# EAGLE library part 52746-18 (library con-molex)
FPC Connector ZIF for SMT 0.5mm Source: http://www.farnell.com/datasheets/73044.pdf [DWG. NO. (Sheet 1 OF 2) SD-52746-**17]
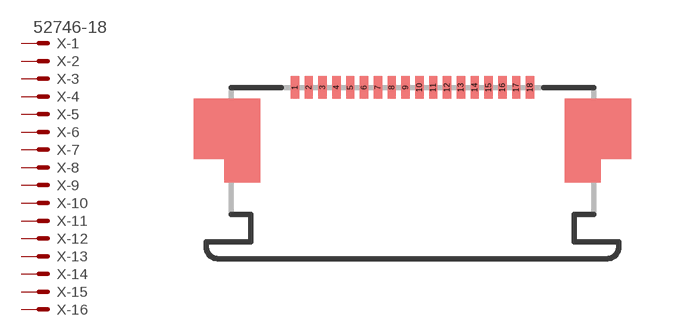
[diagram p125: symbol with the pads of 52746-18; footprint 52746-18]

Designator prefix X; gates -1=MV -2=M -3=M -4=M -5=M -6=M -7=M -8=M -9=M -10=M -11=M -12=M -13=M -14=M -15=M -16=M -17=M -18=M

## 52746-18 (MPN: 52746-1870; OC_FARNELL: unknown; OC_NEWARK: 92M6420)  [52746-18]
1  -1:S  pas
2  -2:S  pas
3  -3:S  pas
4  -4:S  pas
5  -5:S  pas
6  -6:S  pas
7  -7:S  pas
8  -8:S  pas
9  -9:S  pas
10  -10:S  pas
11  -11:S  pas
12  -12:S  pas
13  -13:S  pas
14  -14:S  pas
15  -15:S  pas
16  -16:S  pas
17  -17:S  pas
18  -18:S  pas

## Footprint 52746-18 (pad centres in mm)
FPC Connector ZIF for SMT 0.5mm Source: http://www.farnell.com/datasheets/73044.pdf [DWG. NO. (Sheet 1 OF 2) SD-52746-**17]
smd 0.3 x 0.8: 1 -4.25,0.6; 2 -3.75,0.6; 3 -3.25,0.6; 4 -2.75,0.6; 5 -2.25,0.6; 6 -1.75,0.6; 7 -1.25,0.6; 8 -0.75,0.6; 9 -0.25,0.6; 10 0.25,0.6; 11 0.75,0.6; 12 1.25,0.6; 13 1.75,0.6; 14 2.25,0.6; 15 2.75,0.6; 16 3.25,0.6; 17 3.75,0.6; 18 4.25,0.6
